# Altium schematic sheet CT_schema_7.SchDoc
size 274 x 160 mm
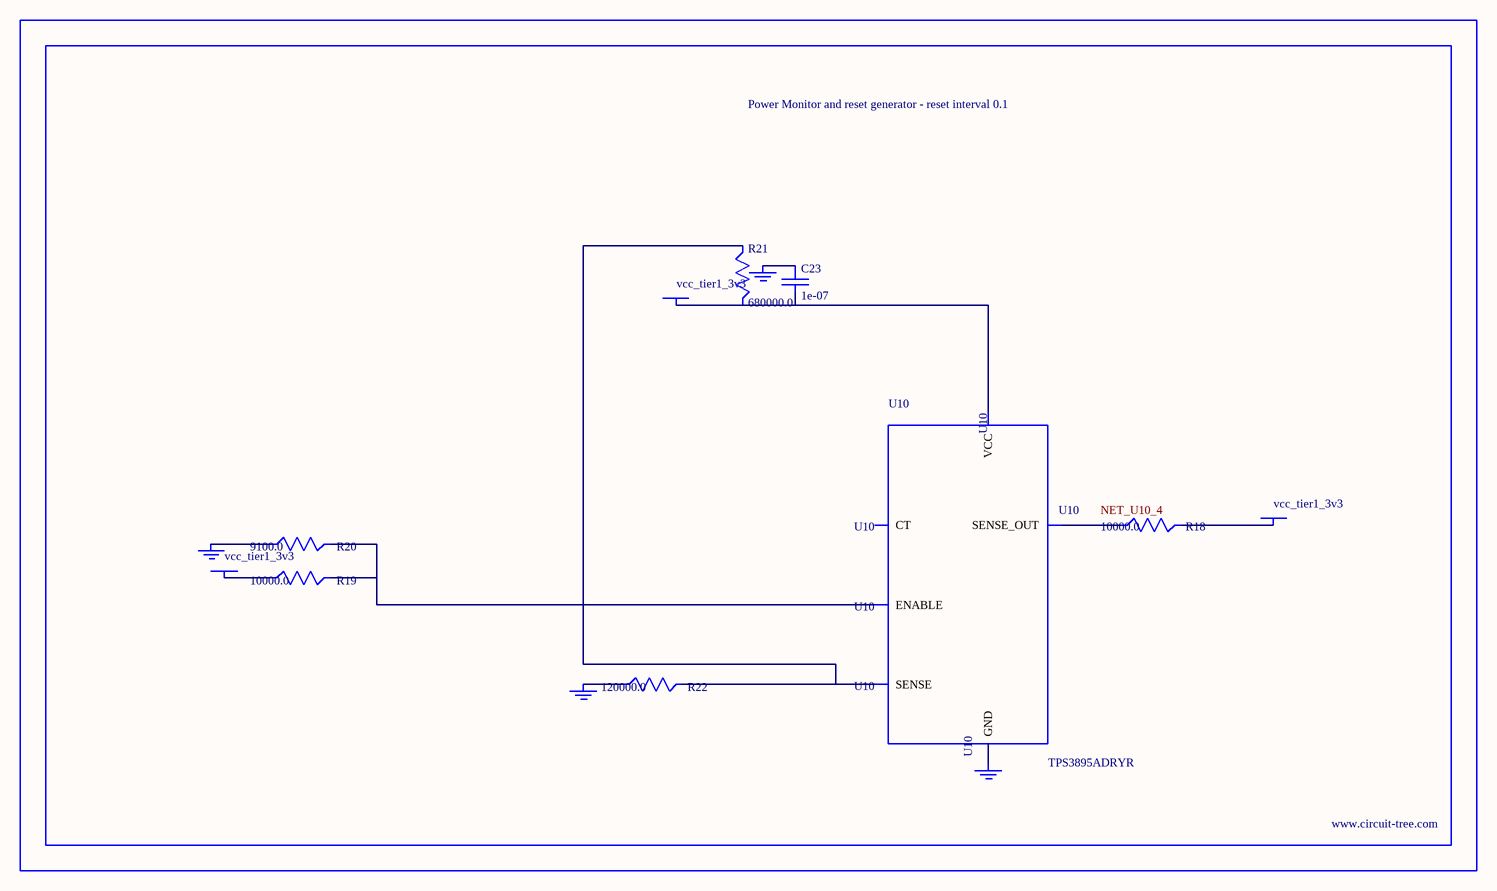
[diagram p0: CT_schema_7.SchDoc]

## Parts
BORDER6  (no value)
C23  1e-07  [C0402]
GND_INSTANCE_6_0  (no value)
GND_INSTANCE_6_1  (no value)
GND_INSTANCE_6_2  (no value)
GND_INSTANCE_6_3  (no value)
POWER_INSTANCE_6_0  vcc_tier1_3v3
POWER_INSTANCE_6_1  vcc_tier1_3v3
POWER_INSTANCE_6_2  vcc_tier1_3v3
R18  10000.0  [R0603]
R19  10000.0  [R0603]
R20  9100.0  [R0603]
R21  680000.0  [R0603]
R22  120000.0  [R0603]
U10  TPS3895ADRYR  [SON-6]

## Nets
NetC23_1: C23.1 GND_INSTANCE_6_2.0(GND)
NetC23_2: C23.2 POWER_INSTANCE_6_2.0(PWR) R21.2 U10.6(VCC)
NetGND_INSTANCE_6_0_0: GND_INSTANCE_6_0.0(GND) R20.1
NetGND_INSTANCE_6_1_0: GND_INSTANCE_6_1.0(GND) R22.1
NetGND_INSTANCE_6_3_0: GND_INSTANCE_6_3.0(GND) U10.2(GND)
NetPOWER_INSTANCE_6_0_0: POWER_INSTANCE_6_0.0(PWR) R19.1
NetPOWER_INSTANCE_6_1_0: POWER_INSTANCE_6_1.0(PWR) R18.2
NetR18_1: R18.1 U10.4(SENSE_OUT)
NetR19_2: R19.2 R20.2 U10.1(ENABLE)
NetR21_1: R21.1 R22.2 U10.3(SENSE)

Not connected (* = marked no-connect by the designer): U10 5(CT)

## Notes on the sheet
- Labels drawn without touching a wire or pin: NET_U10_4

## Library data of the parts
BORDER6 = BORDER_PAGE6
C23 = C0402C104K3RACTU
GND_INSTANCE_6_0-GND_INSTANCE_6_3 = GND
POWER_INSTANCE_6_0-POWER_INSTANCE_6_2 = PWR
R18 R19 = RC0603JR-0710KL
R20 = RC0603JR-079K1L
R21 = RC0603JR-07680KL
R22 = RC0603JR-07120KL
